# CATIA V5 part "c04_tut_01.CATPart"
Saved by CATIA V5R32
Part number: c04tut01
Material "Copper": density 8900 kg/m3, Young's modulus 1.1e+11 Pa, Poisson ratio 0.33, thermal expansion 1.65e-05 1/K
Bounding box of the stored display mesh (mm): x -99.742 to 99.742, y -99.922 to 99.922, z 0 to 140
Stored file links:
  D:\PROJECTS\Project 2022\CATIA V5 6R 2022\Resources\Tutorial Files\c04_catia_v5_6r2022_tut\c04_tut_01.CATPart
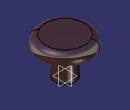
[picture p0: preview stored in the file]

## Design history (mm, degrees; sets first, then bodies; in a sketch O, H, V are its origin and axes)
Body1 (main body), material "Copper"
  Sketch1 on yz-plane, origin (0, 0, 0), H (0, 1, 0), V (0, 0, 1)
    axis line L1 (0, -20) -> (0, 90)
    point P1 (0, -20)
    line L2 (0, 0) -> (0, 140)
    line L3 (0, 140) -> (75, 140)
    arc A1 centre (75, 115) radius 25 from (75, 140) to (66.6667, 91.4298) cw
    arc A2 centre (60, 72.5736) radius 20 from (66.6667, 91.4298) to (40, 72.5736) ccw
    line L4 (40, 72.5736) -> (40, 0)
    point P9 (40, 0)
    line L5 (40, 0) -> (0, 0)
    radius about axis L4 L1 = 40
    radius about axis L1 A1 = 100
    radius A2 = 20
    radius A1 = 25
    distance L5 L3 = 140
    coincidence: P1 V, P9 H, P1 L2
    vertical: L1 V, L2 V
    horizontal: L3 H, L5 H
    tangency: A1 L3, A2 A1, L4 A2
  Shaft1: profile Sketch1, axis Sketch1.L1, angle 360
